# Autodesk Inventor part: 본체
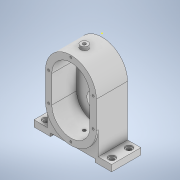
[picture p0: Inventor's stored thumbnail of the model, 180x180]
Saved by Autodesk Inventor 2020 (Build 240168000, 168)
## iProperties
Created: 2021-05
Part Number: 본체
Material: 일반
Document SubType Name: Modeling
Designer: Owner
Density: 1 g/cm^3
Appearance: 기본값
Author: Owner
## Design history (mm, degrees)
sketch "스케치1"
  geometry: L1 (0, 0)-(0, 43); L2 (40, 0)-(40, 43); L3 (-40, 43)-(-40, 0); L4 (0, 83)-(0, -40); A1 r 40 centre (0, 0) between (-40, 0) and (40, 0); A2 r 40 centre (0, 43) between (40, 43) and (-40, 43); 1 further point
  constraints: 10 end point, 6 point on circle, 4 tangent, 2 centre point, 2 midpoint, 2 vertical, 1 parallel
  dimensions: "d0" = 80 distance between parallel lines of L2 L3; "d16" = 123 distance of L4.end L4.start
extrude "돌출1" new body sketch "스케치1" distance "d3" = 49; taper "d4" = 0 deg
sketch "스케치2"
  geometry: 1 further point
feature "쉘2" dims "d10" = 10
node "작업 평면2"
sketch "스케치6"
  geometry: L1 (61, 46)-(-61, 46); L2 (-61, 46)-(-61, 0); L3 (-61, 0)-(61, 0); L4 (61, 0)-(61, 46); L5 (40, 0)-(-40, 0) reference; 5 further points
  constraints: 8 end point, 3 midpoint, 3 parallel, 2 horizontal, 1 perpendicular, 4 other
  dimensions: "d12" = 122 distance of L2.end L3.end; "d13" = 46 distance of L3.end L1.start
extrude "돌출2" join sketch "스케치6" distance "d14" = 10; taper "d15" = 0 deg
sketch "스케치7"
  geometry: L1 (76.199, 10)-(122, 10) reference; L2 (101, 47)-(101, 10); A1 r 40 centre (61, 47) between (76.199, 10) and (101, 47) reference; 1 further point
  constraints: 2 end point, 1 perpendicular, 1 point on circle, 1 point on line, 1 tangent
extrude "돌출3" join sketch "스케치7" distance "d18" = 46; taper "d19" = 0 deg
node "작업 평면4"
sketch "스케치8"
  geometry: L1 (40, 49)-(-40, 49) reference; C1 r 6 at (0, 28); 1 further point
  constraints: 1 centre point, 1 vertical alignment
  dimensions: "d21" = 12 diameter of C1; "d22" = 21 distance from line of L1 C1.centre
extrude "돌출4" join sketch "스케치8" stored distance "d23" = 46; taper "d24" = 0 deg
sketch "스케치9"
  geometry: L1 (0, 0)-(0, 45); L2 (-26, 0)-(-26, 45); L3 (26, 45)-(26, 0); A1 r 26 centre (0, 0) between (-26, 0) and (26, 0); A2 r 26 centre (0, 45) between (26, 45) and (-26, 45); 1 further point
  constraints: 8 end point, 4 point on circle, 4 tangent, 2 centre point, 1 midpoint, 1 parallel, 1 vertical
  dimensions: "d25" = 52 distance between parallel lines of L3 L2; "d26" = 45 distance of L1.start L1.end
extrude "돌출5" join sketch "스케치9" distance "d27" = 11; taper "d28" = 0 deg
sketch "스케치10"
  geometry: L1 (-26, 45)-(-26, 0) reference; L2 (26, 0)-(26, 45) reference; L3 (-26, 45)-(-26, 0) reference; L4 (26, 0)-(26, 45) reference; L5 (-26, 0)-(-26, 45) reference; L6 (-26, 15)-(26, 15); A1 r 26 centre (0, 45) between (26, 45) and (-26, 45) reference; A2 r 26 centre (0, 0) between (-26, 0) and (26, 0) reference; A3 r 26 centre (0, 45) between (26, 45) and (-26, 45) reference; 3 further points
  constraints: 2 end point, 2 point on line, 1 perpendicular
  dimensions: "d29" = 30 distance from line of L6 A1.centre
extrude "돌출6" cut sketch "스케치10" distance "d30" = 3; taper "d31" = 0 deg
sketch "스케치11"
  geometry: 2 further points
  constraints: 1 coincident
hole "구멍1" sketch "스케치11" at (0, 0) diameter "d32" = 20; stored, may be unused: countersink angle "d36" = 90 deg, drill point angle "d38" = 0 deg; dims "d33" = 6, "d34" = 28, "d35" = 8, "d37" = 12
sketch "스케치12"
  geometry: 2 further points
  constraints: 1 vertical alignment
  dimensions: "d39" = 45 distance of point (0, 0) point (0, 45)
hole "구멍2" sketch "스케치12" at (0, 45) diameter "d40" = 22; stored, may be unused: countersink angle "d44" = 90 deg, drill point angle "d46" = 0 deg; dims "d41" = 6, "d42" = 28, "d43" = 8, "d45" = 12
sketch "스케치13"
  geometry: C1 r 11 at (0, 45) reference; 2 further points
  constraints: 1 coincident
hole "구멍3" sketch "스케치13" at (0, 45) diameter "d47" = 22; stored, may be unused: countersink angle "d51" = 90 deg, drill point angle "d53" = 0 deg; dims "d48" = 6, "d49" = 28, "d50" = 4, "d52" = 6
sketch "스케치14"
  geometry: 1 further point
sketch "스케치15"
  geometry: 2 further points
hole "구멍4" sketch "스케치15" at (0.082, -0.154) diameter "d54" = 4.917; stored, may be unused: countersink angle "d58" = 90 deg, drill point angle "d60" = 0 deg; dims "d55" = 12, "d56" = 28, "d57" = 4, "d59" = 17.1
sketch "스케치16"
  geometry: 2 further points
  constraints: 1 vertical alignment
  dimensions: "d61" = 35 distance of point (0, 0) point (0, -35)
hole "구멍5" sketch "스케치16" at (0, -35) diameter "d62" = 3.242; stored, may be unused: countersink angle "d66" = 90 deg, drill point angle "d68" = 118 deg; dims "d63" = 8, "d64" = 28, "d65" = 4, "d67" = 10
sketch "스케치17"
  geometry: 3 further points
  constraints: 2 horizontal alignment
  dimensions: "d69" = 35 distance of point (0, 0) point (-35, 0); "d70" = 35 distance of point (35, 0) point (0, 0)
hole "구멍6" sketch "스케치17" at (-35, 0), (35, 0) diameter "d71" = 3.242; stored, may be unused: countersink angle "d75" = 90 deg, drill point angle "d77" = 118 deg; dims "d72" = 8, "d73" = 28, "d74" = 4, "d76" = 10
sketch "스케치18"
  geometry: L1 (0, 82.682)-(0, 19.286); 4 further points
  constraints: 2 end point, 1 point on line, 1 vertical, 1 vertical alignment
  dimensions: "d79" = 35 horizontal distance of point (0, 0) point (-35, 45); "d80" = 35 horizontal distance of point (0, 0) point (35, 45); "d81" = 80 distance of point (0, 0) point (0, 80); "d82" = 45 vertical distance of point (0, 0) point (35, 45); "d83" = 45 vertical distance of point (0, 0) point (-35, 45)
hole "구멍7" sketch "스케치18" at (-35, 45), (0, 80), (35, 45) diameter "d84" = 3.242; stored, may be unused: countersink angle "d88" = 90 deg, drill point angle "d90" = 118 deg; dims "d85" = 8, "d86" = 28, "d87" = 4, "d89" = 10
sketch "스케치19"
  geometry: L1 (-61, 46)-(61, 46) reference; L2 (-35, 46)-(-35, 0); L3 (35, 46)-(35, 0); L4 (40, 0)-(-40, 0) reference; L5 (0, 82.582)-(0, -32.484); 5 further points
  constraints: 6 end point, 4 point on line, 3 vertical, 1 midpoint, 4 other
  dimensions: "d91" = 70 distance between parallel lines of L3 L2
extrude "돌출7" cut sketch "스케치19" distance "d92" = 5; taper "d93" = 0 deg
sketch "스케치20"
  geometry: 5 further points
hole "구멍8" sketch "스케치20" at (-51.424, -9.657), (-51.424, -36.697), (52.125, -36.697), (52.125, -9.657) diameter "d94" = 6.6; stored, may be unused: countersink angle "d98" = 90 deg, drill point angle "d100" = 0 deg; dims "d95" = 8, "d96" = 11, "d97" = 2, "d99" = 10
sketch "스케치21"
  geometry: C1 r 11 at (0, 45) reference; 2 further points
  constraints: 1 vertical alignment
  dimensions: "d101" = 20 distance of C1.centre point (0, 65)
hole "구멍9" sketch "스케치21" at (0, 65) diameter "d102" = 3.242; stored, may be unused: countersink angle "d106" = 90 deg, drill point angle "d108" = 118 deg; dims "d103" = 8, "d104" = 11, "d105" = 2, "d107" = 10
sketch "스케치22"
  geometry: C1 r 6 at (0, 28) reference; 2 further points
  constraints: 1 coincident
hole "구멍10" sketch "스케치22" at (0, 28) diameter "d112" = 4.917; stored, may be unused: countersink angle "d116" = 90 deg, drill point angle "d118" = 118 deg; dims "d113" = 12, "d114" = 12, "d115" = 1, "d117" = 17.1
node "솔리드1"
mirror "미러1"
pattern_circular "원형 패턴1" dims angle "d110" = 360 deg
node "투영된 루프1"
feature "A9D066F2-1C7D-4E18-AEED-F7BC21143FA4" dims "d40" = 22, "d41" = 6, "d42" = 28, "d43" = 8, "d44" = 90 deg, "d45" = 12, "d46" = 0
other parameters: "d11" = -47, "d20" = 88
